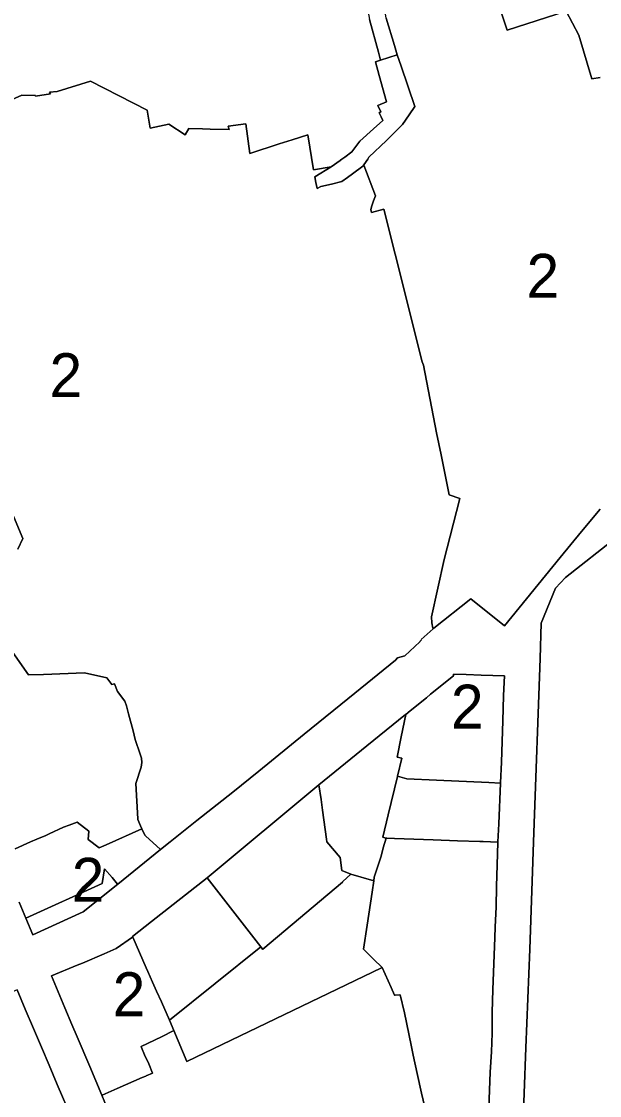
# Model space of a CAD drawing. Extents: x 598968 to 613553, y 4409678 to 4430833.
# Drawn here: x 608010.1 to 608168.2, y 4415786.4 to 4416080 of the extents above; entities that cross this region are included whole.
import ezdxf

# ---------------------------------------------------------------- set-up
doc = ezdxf.new("R2010")
doc.units = 0
doc.layers.add('1', color=7, linetype='Continuous')
doc.layers.add('ZONA 2. CARRERS DE CASES. Cases de trast', color=7, linetype='Continuous')

msp = doc.modelspace()

# ---------------------------------------------------------------- linework, layer by layer
at = {"layer": '1'}
for points in [[(608137.1627, 4416094.9227), (608142.8727, 4416077.613), (608159.0125, 4416082.8533), (608162.5225, 4416076.2184), (608166.0325, 4416064.3536), (608168.3725, 4416064.7236)], [(608007.1647, 4415908.4327), (608012.0547, 4415901.3929), (608016.1497, 4415901.553), (608027.3745, 4415901.9931), (608033.4945, 4415900.5733), (608034.8733, 4415898.8033), (608035.5158, 4415898.9755), (608036.3744, 4415896.8634), (608038.4244, 4415894.1934), (608038.7944, 4415892.9435), (608039.4144, 4415890.7335), (608040.6294, 4415886.0735), (608041.2444, 4415883.7135), (608042.5944, 4415879.7386), (608042.9644, 4415878.6036), (608043.0044, 4415877.4136), (608042.8344, 4415876.2236), (608041.4145, 4415871.6937), (608041.9245, 4415862.0838), (608041.9545, 4415861.8438), (608042.6845, 4415860.1338), (608043.0163, 4415859.2813), (608043.0318, 4415859.2414), (608043.961, 4415857.5059), (608044.0347, 4415857.4437), (608048.1533, 4415853.693), (608050.7492, 4415855.7372), (608058.0743, 4415861.5741), (608067.8643, 4415869.3842), (608074.9942, 4415875.0542), (608087.414, 4415885.1693), (608101.2288, 4415896.3845), (608112.3436, 4415905.4046), (608112.9636, 4415906.0846), (608114.9736, 4415906.6047), (608119.0206, 4415910.3939), (608119.0935, 4415910.6647), (608119.4573, 4415910.9623), (608119.3735, 4415911.0647), (608122.6655, 4415914.0339), (608122.6235, 4415914.2147), (608122.2935, 4415915.6347), (608122.2135, 4415917.2947), (608125.6534, 4415932.9645), (608127.3583, 4415939.3245), (608129.9333, 4415949.5944), (608127.0155, 4415950.6343), (608124.8433, 4415961.5789), (608123.6233, 4415967.5341), (608119.9968, 4415986.075), (608119.6733, 4415986.9738), (608118.0333, 4415993.4837), (608113.3733, 4416012.1133), (608112.3044, 4416016.3864), (608109.2333, 4416028.6631), (608105.7933, 4416027.783), (608105.6633, 4416028.633), (608105.8733, 4416029.583), (608106.3983, 4416030.958), (608106.9233, 4416032.333), (608103.7528, 4416040.7511), (608103.7338, 4416040.8017), (608103.4933, 4416040.4428), (608100.6133, 4416038.3328), (608099.2581, 4416037.34), (608097.7334, 4416036.2228), (608094.8434, 4416035.5627), (608091.9534, 4416034.9027), (608090.9735, 4416034.3927), (608090.6335, 4416035.9877), (608090.2935, 4416037.5826), (608094.8134, 4416040.2827), (608090.0034, 4416039.4926), (608088.4134, 4416049.0624), (608084.1407, 4416047.6815), (608080.6116, 4416046.541), (608072.5836, 4416043.9422), (608071.4328, 4416052.0491), (608066.6676, 4416051.382), (608066.8836, 4416050.492), (608061.7236, 4416050.5819), (608059.6136, 4416050.6401), (608055.9237, 4416050.7418), (608054.8957, 4416048.9819), (608050.4538, 4416051.9217), (608045.3005, 4416050.8316), (608044.4438, 4416055.7915), (608028.984, 4416063.7212), (608019.8441, 4416060.891), (608017.8241, 4416060.671), (608018.0341, 4416060.261), (608013.9742, 4416059.551), (608013.9142, 4416059.751), (608010.1842, 4416059.8409), (608000.1743, 4416055.4108)], [(608147.1372, 4415774.7218), (608147.9912, 4415799.469), (608149.0735, 4415826.4461), (608150.1634, 4415858.3058), (608151.9532, 4415905.9053), (608152.2432, 4415915.5152), (608156.1031, 4415925.0852), (608158.818, 4415928.0352), (608173.0029, 4415939.1103), (608195.6825, 4415957.6355), (608200.3524, 4415960.8055), (608221.6822, 4415930.7563), (608255.222, 4415883.0623), (608272.9401, 4415858.0517), (608249.6939, 4415844.9262), (608244.7573, 4415842.1383), (608223.8617, 4415831.0564), (608223.318, 4415824.7504), (608232.177, 4415812.6025), (608239.1802, 4415802.6277), (608239.1774, 4415802.6257), (608245.5873, 4415793.7606), (608255.3608, 4415780.109)], [(608007.9446, 4415944.7523), (608010.5146, 4415938.7024), (608009.1296, 4415935.7374)], [(608168.3678, 4415946.6701), (608163.2229, 4415940.6151), (608157.4016, 4415933.4974), (608142.1632, 4415914.805), (608132.9633, 4415922.1948), (608122.8335, 4415914.1947), (608122.7063, 4415914.073), (608122.6655, 4415914.0339), (608119.3735, 4415911.0647), (608119.4573, 4415910.9623), (608119.0935, 4415910.6647), (608119.0206, 4415910.3939), (608114.9736, 4415906.6047), (608112.9636, 4415906.0846), (608112.3436, 4415905.4046), (608101.2288, 4415896.3845), (608087.414, 4415885.1693), (608074.9942, 4415875.0542), (608067.8643, 4415869.3842), (608058.0743, 4415861.5741), (608050.7492, 4415855.7372), (608048.1533, 4415853.693), (608036.4246, 4415844.2161), (608036.4136, 4415844.207), (608036.4246, 4415844.1939), (608026.9948, 4415836.6038), (608013.2566, 4415830.3561), (608011.2949, 4415834.8936), (608009.5149, 4415839.2363)], [(608033.7722, 4415782.5175), (608032.1214, 4415786.5356), (608032.1351, 4415786.5416), (608028.826, 4415794.3462), (608025.3849, 4415802.4442), (608023.9283, 4415805.8681), (608021.9829, 4415810.4422), (608018.2949, 4415819.1139), (608025.3662, 4415822.0551), (608026.7852, 4415822.6453), (608032.7377, 4415825.1212), (608034.3797, 4415825.8641), (608036.0163, 4415826.6052), (608040.5072, 4415829.6971), (608040.5359, 4415829.7197), (608040.4535, 4415829.9076), (608045.6633, 4415833.9978), (608060.8702, 4415845.9364), (608091.4324, 4415871.3281), (608104.5288, 4415882.0231), (608115.1189, 4415890.5404), (608115.1836, 4415890.5849), (608116.3836, 4415891.5549), (608120.8987, 4415895.1449), (608121.9647, 4415896.1731), (608128.2527, 4415901.1043), (608128.2735, 4415901.615), (608131.7386, 4415901.4905), (608135.7734, 4415901.3551), (608142.2211, 4415901.1477), (608141.9324, 4415895.7677), (608141.8608, 4415892.2114), (608141.7333, 4415888.8052), (608141.5634, 4415883.1753), (608141.3934, 4415877.5054), (608141.07, 4415871.8906), (608141.0682, 4415871.844), (608140.6272, 4415860.7309), (608140.622, 4415860.7312), (608140.3335, 4415855.8087), (608140.3335, 4415855.6956), (608140.1672, 4415849.4154), (608139.9763, 4415843.6596), (608139.8635, 4415837.9158), (608139.6286, 4415832.4947), (608139.4991, 4415829.5345), (608139.2552, 4415822.4766), (608139.0025, 4415815.2799), (608138.8549, 4415809.169), (608138.8074, 4415803.4512), (608138.5984, 4415798.3517), (608138.2659, 4415792.7834), (608138.0937, 4415787.8564), (608137.9337, 4415782.8965)], [(608009.5149, 4415839.2363), (608011.2949, 4415834.8936), (608032.1749, 4415844.3438), (608032.8605, 4415848.4097), (608032.8646, 4415848.4338), (608034.876, 4415846.0383), (608036.4136, 4415844.207), (608036.4246, 4415844.2161), (608048.1533, 4415853.693), (608044.0347, 4415857.4437), (608043.961, 4415857.5059), (608043.0318, 4415859.2414), (608043.0163, 4415859.2813), (608033.3193, 4415854.9739), (608031.4052, 4415854.1237), (608028.3347, 4415856.4336), (608028.5347, 4415858.6636), (608025.3785, 4415861.1871), (608023.1269, 4415860.3168), (608021.6516, 4415859.7466), (608017.6524, 4415857.9245), (608016.7851, 4415857.5294), (608014.3395, 4415856.4769), (608012.6207, 4415855.7371), (608008.3628, 4415853.8652)], [(608120.4151, 4415783.2505), (608119.5239, 4415787.1161), (608118.3439, 4415792.476), (608117.1939, 4415797.4659), (608116.6344, 4415800.2111), (608114.8339, 4415809.0457), (608113.6485, 4415813.971), (608113.5767, 4415813.9671), (608112.2785, 4415813.8958), (608112.1899, 4415813.8909), (608112.0939, 4415813.8856), (608111.1745, 4415815.9791), (608108.7739, 4415821.4455), (608108.5654, 4415821.3452), (608055.3581, 4415795.7388), (608051.7749, 4415804.1641), (608048.4446, 4415802.4346), (608042.8282, 4415799.8516), (608042.8182, 4415799.8468), (608042.9441, 4415799.5619), (608043.7347, 4415797.5846), (608044.8997, 4415795.1046), (608045.9576, 4415792.5789), (608044.1961, 4415791.826), (608044.1247, 4415791.7247), (608043.1047, 4415791.3647), (608036.2841, 4415788.3659), (608032.1481, 4415786.5111), (608032.1351, 4415786.5416), (608032.1214, 4415786.5356), (608033.7722, 4415782.5175)], [(608008.955, 4415815.2738), (608011.165, 4415810.0739), (608013.405, 4415804.794), (608015.575, 4415799.6841), (608017.685, 4415794.6942), (608019.9106, 4415789.4679), (608023.9588, 4415779.9845)]]:
    msp.add_lwpolyline(points, dxfattribs=at)
for points in [[(608103.7338, 4416040.8017), (608104.7933, 4416042.3728), (608105.0733, 4416042.8928), (608109.8785, 4416047.4493), (608114.3231, 4416051.8428), (608116.0828, 4416054.453), (608117.6331, 4416056.7528), (608113.886, 4416067.759), (608112.8231, 4416070.8826), (608108.302, 4416069.4164), (608108.3031, 4416069.4125), (608106.9332, 4416068.9725), (608107.9587, 4416065.2499), (608109.9332, 4416058.0827), (608107.5432, 4416057.0527), (608108.3832, 4416055.3027), (608107.9232, 4416055.0727), (608108.4355, 4416053.9078), (608108.8732, 4416052.9127), (608106.3831, 4416050.6628), (608102.6533, 4416047.2927), (608100.4733, 4416044.3427), (608098.5377, 4416042.9514), (608097.749, 4416042.3852), (608097.383, 4416042.1233), (608097.2603, 4416042.0354), (608094.8134, 4416040.2827), (608090.2935, 4416037.5826), (608090.6335, 4416035.9877), (608090.9735, 4416034.3927), (608091.9534, 4416034.9027), (608094.8434, 4416035.5627), (608097.7334, 4416036.2228), (608099.2581, 4416037.34), (608100.6133, 4416038.3328), (608103.4933, 4416040.4428)], [(608112.9674, 4415873.7341), (608112.9698, 4415873.7442), (608114.123, 4415878.6054), (608112.8434, 4415878.9154), (608113.9395, 4415884.5147), (608115.1836, 4415890.5849), (608115.1189, 4415890.5404), (608104.5288, 4415882.0231), (608091.4324, 4415871.3281), (608092.0557, 4415867.3049), (608092.4378, 4415864.4486), (608093.524, 4415856.4948), (608093.594, 4415855.8048), (608097.284, 4415851.4749), (608097.684, 4415847.975), (608100.214, 4415846.895), (608106.441, 4415845.0789), (608106.4539, 4415845.0751), (608106.5939, 4415846.1251), (608108.4238, 4415851.8551), (608109.0465, 4415854.091), (608109.7878, 4415856.753), (608109.7485, 4415856.7661), (608108.9138, 4415857.045), (608110.3975, 4415863.1524), (608112.9333, 4415873.5922)], [(608141.0682, 4415871.844), (608137.9345, 4415871.9792), (608123.5762, 4415872.5985), (608115.5044, 4415872.9467), (608112.9674, 4415873.7341), (608112.9333, 4415873.5922), (608110.3975, 4415863.1524), (608108.9138, 4415857.045), (608109.7485, 4415856.7661), (608109.9872, 4415856.759), (608112.1338, 4415856.6951), (608122.7137, 4415856.3455), (608129.3336, 4415856.0654), (608135.4135, 4415855.8355), (608136.3184, 4415855.8307), (608140.3335, 4415855.6956), (608140.3335, 4415855.8087), (608140.622, 4415860.7312), (608140.6272, 4415860.7309)], [(608100.214, 4415846.895), (608097.684, 4415847.975), (608097.284, 4415851.4749), (608093.594, 4415855.8048), (608093.524, 4415856.4948), (608092.4378, 4415864.4486), (608092.0557, 4415867.3049), (608091.4324, 4415871.3281), (608060.8702, 4415845.9364), (608075.5541, 4415827.0746), (608075.6111, 4415827.0065), (608076.0653, 4415826.4691), (608076.0865, 4415826.4435), (608097.864, 4415844.775), (608098.004, 4415844.905)], [(608075.5541, 4415827.0746), (608060.8702, 4415845.9364), (608045.6633, 4415833.9978), (608040.4535, 4415829.9076), (608040.5359, 4415829.7197), (608044.1884, 4415821.3598), (608044.6401, 4415820.3367), (608045.9068, 4415817.457), (608046.6524, 4415815.769), (608047.0126, 4415814.988), (608048.3746, 4415812.0345), (608050.5851, 4415806.9903)], [(608104.634, 4415832.9826), (608105.9869, 4415841.9721), (608106.4539, 4415845.0751), (608106.441, 4415845.0789), (608100.214, 4415846.895), (608098.004, 4415844.905), (608097.864, 4415844.775), (608076.0865, 4415826.4435), (608076.0653, 4415826.4691), (608075.6111, 4415827.0065), (608075.5541, 4415827.0746), (608050.5851, 4415806.9903), (608051.8146, 4415804.1847), (608051.7749, 4415804.1641), (608055.3581, 4415795.7388), (608108.5654, 4415821.3452), (608108.7739, 4415821.4455), (608106.4062, 4415823.7347), (608103.644, 4415826.4053)]]:
    msp.add_lwpolyline(points, close=True, dxfattribs=at)
at = {"layer": 'ZONA 2. CARRERS DE CASES. Cases de trast'}
for points in [[(608168.3725, 4416064.7236), (608166.0325, 4416064.3536), (608162.5225, 4416076.2184), (608159.0125, 4416082.8533), (608142.8727, 4416077.613), (608137.1627, 4416094.9227)], [(608000.1743, 4416055.4108), (608010.1842, 4416059.8409), (608013.9142, 4416059.751), (608013.9742, 4416059.551), (608018.0341, 4416060.261), (608017.8241, 4416060.671), (608019.8441, 4416060.891), (608028.984, 4416063.7212), (608044.4438, 4416055.7915), (608045.3005, 4416050.8316), (608050.4538, 4416051.9217), (608054.8957, 4416048.9819), (608055.9237, 4416050.7418), (608059.6136, 4416050.6401), (608061.7236, 4416050.5819), (608066.8836, 4416050.492), (608066.6676, 4416051.382), (608071.4328, 4416052.0491), (608072.5836, 4416043.9422), (608080.6116, 4416046.541), (608084.1407, 4416047.6815), (608088.4134, 4416049.0624), (608090.0034, 4416039.4926), (608094.8134, 4416040.2827), (608097.2603, 4416042.0354), (608097.383, 4416042.1233), (608097.749, 4416042.3852), (608098.5377, 4416042.9514), (608100.4733, 4416044.3427), (608102.6533, 4416047.2927), (608106.3831, 4416050.6628), (608108.8732, 4416052.9127), (608108.4355, 4416053.9078), (608107.9232, 4416055.0727), (608108.3832, 4416055.3027), (608107.5432, 4416057.0527), (608109.9332, 4416058.0827), (608107.9587, 4416065.2499), (608106.9332, 4416068.9725), (608108.3031, 4416069.4125), (608108.302, 4416069.4164), (608107.718, 4416071.5771), (608105.3031, 4416080.5123)], [(608109.8531, 4416080.8724), (608112.0714, 4416073.4108), (608112.8231, 4416070.8826), (608113.886, 4416067.759), (608117.6331, 4416056.7528), (608116.0828, 4416054.453), (608114.3231, 4416051.8428), (608109.8785, 4416047.4493), (608105.0733, 4416042.8928), (608104.7933, 4416042.3728), (608103.7338, 4416040.8017), (608103.7528, 4416040.7511), (608106.9233, 4416032.333), (608106.3983, 4416030.958), (608105.8733, 4416029.583), (608105.6633, 4416028.633), (608105.7933, 4416027.783), (608109.2333, 4416028.6631), (608112.3044, 4416016.3864), (608113.3733, 4416012.1133), (608118.0333, 4415993.4837), (608119.6733, 4415986.9738), (608119.9968, 4415986.075), (608123.6233, 4415967.5341), (608124.8433, 4415961.5789), (608127.0155, 4415950.6343), (608129.9333, 4415949.5944), (608127.3583, 4415939.3245), (608125.6534, 4415932.9645), (608122.2135, 4415917.2947), (608122.2935, 4415915.6347), (608122.6235, 4415914.2147), (608122.6655, 4415914.0339), (608122.7063, 4415914.073), (608122.8335, 4415914.1947), (608132.9633, 4415922.1948), (608142.1632, 4415914.805), (608157.4016, 4415933.4974), (608163.2229, 4415940.6151), (608168.3678, 4415946.6701)], [(608255.3608, 4415780.109), (608245.5873, 4415793.7606), (608239.1774, 4415802.6257), (608239.1802, 4415802.6277), (608232.177, 4415812.6025), (608223.318, 4415824.7504), (608223.8617, 4415831.0564), (608244.7573, 4415842.1383), (608249.6939, 4415844.9262), (608272.9401, 4415858.0517), (608255.222, 4415883.0623), (608221.6822, 4415930.7563), (608200.3524, 4415960.8055), (608195.6825, 4415957.6355), (608173.0029, 4415939.1103), (608158.818, 4415928.0352), (608156.1031, 4415925.0852), (608152.2432, 4415915.5152), (608151.9532, 4415905.9053), (608150.1634, 4415858.3058), (608149.0735, 4415826.4461), (608147.9912, 4415799.469), (608147.1372, 4415774.7218)], [(608009.1296, 4415935.7374), (608010.5146, 4415938.7024), (608007.9446, 4415944.7523)], [(608008.3628, 4415853.8652), (608012.6207, 4415855.7371), (608014.3395, 4415856.4769), (608016.7851, 4415857.5294), (608017.6524, 4415857.9245), (608021.6516, 4415859.7466), (608023.1269, 4415860.3168), (608025.3785, 4415861.1871), (608028.5347, 4415858.6636), (608028.3347, 4415856.4336), (608031.4052, 4415854.1237), (608033.3193, 4415854.9739), (608043.0163, 4415859.2813), (608042.6845, 4415860.1338), (608041.9545, 4415861.8438), (608041.9245, 4415862.0838), (608041.4145, 4415871.6937), (608042.8344, 4415876.2236), (608043.0044, 4415877.4136), (608042.9644, 4415878.6036), (608042.5944, 4415879.7386), (608041.2444, 4415883.7135), (608040.6294, 4415886.0735), (608039.4144, 4415890.7335), (608038.7944, 4415892.9435), (608038.4244, 4415894.1934), (608036.3744, 4415896.8634), (608035.5158, 4415898.9755), (608034.8733, 4415898.8033), (608033.4945, 4415900.5733), (608027.3745, 4415901.9931), (608016.1497, 4415901.553), (608012.0547, 4415901.3929), (608007.1647, 4415908.4327)], [(608137.9337, 4415782.8965), (608138.0937, 4415787.8564), (608138.2659, 4415792.7834), (608138.5984, 4415798.3517), (608138.8074, 4415803.4512), (608138.8549, 4415809.169), (608139.0025, 4415815.2799), (608139.2552, 4415822.4766), (608139.4991, 4415829.5345), (608139.6286, 4415832.4947), (608139.8635, 4415837.9158), (608139.9763, 4415843.6596), (608140.1672, 4415849.4154), (608140.3335, 4415855.6956), (608136.3184, 4415855.8307), (608135.4135, 4415855.8355), (608129.3336, 4415856.0654), (608122.7137, 4415856.3455), (608112.1338, 4415856.6951), (608109.9872, 4415856.759), (608109.7485, 4415856.7661), (608109.7878, 4415856.753), (608109.0465, 4415854.091), (608108.4238, 4415851.8551), (608106.5939, 4415846.1251), (608106.4539, 4415845.0751), (608105.9869, 4415841.9721), (608104.634, 4415832.9826), (608103.644, 4415826.4053), (608106.4062, 4415823.7347), (608108.7739, 4415821.4455), (608111.1745, 4415815.9791), (608112.0939, 4415813.8856), (608112.1899, 4415813.8909), (608112.2785, 4415813.8958), (608113.5767, 4415813.9671), (608113.6485, 4415813.971), (608114.8339, 4415809.0457), (608116.6344, 4415800.2111), (608117.1939, 4415797.4659), (608118.3439, 4415792.476), (608119.5239, 4415787.1161), (608120.4151, 4415783.2505)], [(608023.9588, 4415779.9845), (608019.9106, 4415789.4679), (608017.685, 4415794.6942), (608015.575, 4415799.6841), (608013.405, 4415804.794), (608011.165, 4415810.0739), (608008.955, 4415815.2738), (607993.0752, 4415808.6936), (607986.6753, 4415805.9835), (607987.1734, 4415804.8865), (607987.02, 4415804.8539), (608001.049, 4415770.7826)]]:
    msp.add_lwpolyline(points, dxfattribs=at)
for points in [[(608112.8231, 4416070.8826), (608112.0714, 4416073.4108), (608109.8531, 4416080.8724), (608109.3248, 4416084.4423), (608108.2581, 4416091.6507), (608103.3862, 4416091.0948), (608105.3031, 4416080.5123), (608107.718, 4416071.5771), (608108.302, 4416069.4164)], [(608141.0682, 4415871.844), (608141.07, 4415871.8906), (608141.3934, 4415877.5054), (608141.5634, 4415883.1753), (608141.7333, 4415888.8052), (608141.8608, 4415892.2114), (608141.9324, 4415895.7677), (608142.2211, 4415901.1477), (608135.7734, 4415901.3551), (608131.7386, 4415901.4905), (608128.2735, 4415901.615), (608128.2527, 4415901.1043), (608121.9647, 4415896.1731), (608120.8987, 4415895.1449), (608116.3836, 4415891.5549), (608115.1836, 4415890.5849), (608113.9395, 4415884.5147), (608112.8434, 4415878.9154), (608114.123, 4415878.6054), (608112.9698, 4415873.7442), (608112.9674, 4415873.7341), (608115.5044, 4415872.9467), (608123.5762, 4415872.5985), (608137.9345, 4415871.9792)], [(608036.4136, 4415844.207), (608034.876, 4415846.0383), (608032.8646, 4415848.4338), (608032.8605, 4415848.4097), (608032.1749, 4415844.3438), (608011.2949, 4415834.8936), (608013.2566, 4415830.3561), (608026.9948, 4415836.6038), (608036.4246, 4415844.1939)], [(608047.0126, 4415814.988), (608046.6524, 4415815.769), (608045.9068, 4415817.457), (608044.6401, 4415820.3367), (608044.1884, 4415821.3598), (608040.5359, 4415829.7197), (608040.5072, 4415829.6971), (608036.0163, 4415826.6052), (608034.3797, 4415825.8641), (608032.7377, 4415825.1212), (608026.7852, 4415822.6453), (608025.3662, 4415822.0551), (608018.2949, 4415819.1139), (608021.9829, 4415810.4422), (608023.9283, 4415805.8681), (608025.3849, 4415802.4442), (608028.826, 4415794.3462), (608032.1351, 4415786.5416), (608032.1481, 4415786.5111), (608036.2841, 4415788.3659), (608043.1047, 4415791.3647), (608044.1247, 4415791.7247), (608044.1961, 4415791.826), (608045.9576, 4415792.5789), (608044.8997, 4415795.1046), (608043.7347, 4415797.5846), (608042.9441, 4415799.5619), (608042.8182, 4415799.8468), (608042.8282, 4415799.8516), (608048.4446, 4415802.4346), (608051.7749, 4415804.1641), (608051.8146, 4415804.1847), (608050.5851, 4415806.9903), (608048.3746, 4415812.0345)]]:
    msp.add_lwpolyline(points, close=True, dxfattribs=at)

# ---------------------------------------------------------------- texts
for p in [(608148.2089, 4416004.4783), (608017.7942, 4415977.3268), (608127.5322, 4415886.7295), (608023.8597, 4415839.395), (608035.0548, 4415808.1154)]:
    msp.add_text('2', height=12, dxfattribs=at).set_placement(p)

doc.saveas('drawing.dxf')
